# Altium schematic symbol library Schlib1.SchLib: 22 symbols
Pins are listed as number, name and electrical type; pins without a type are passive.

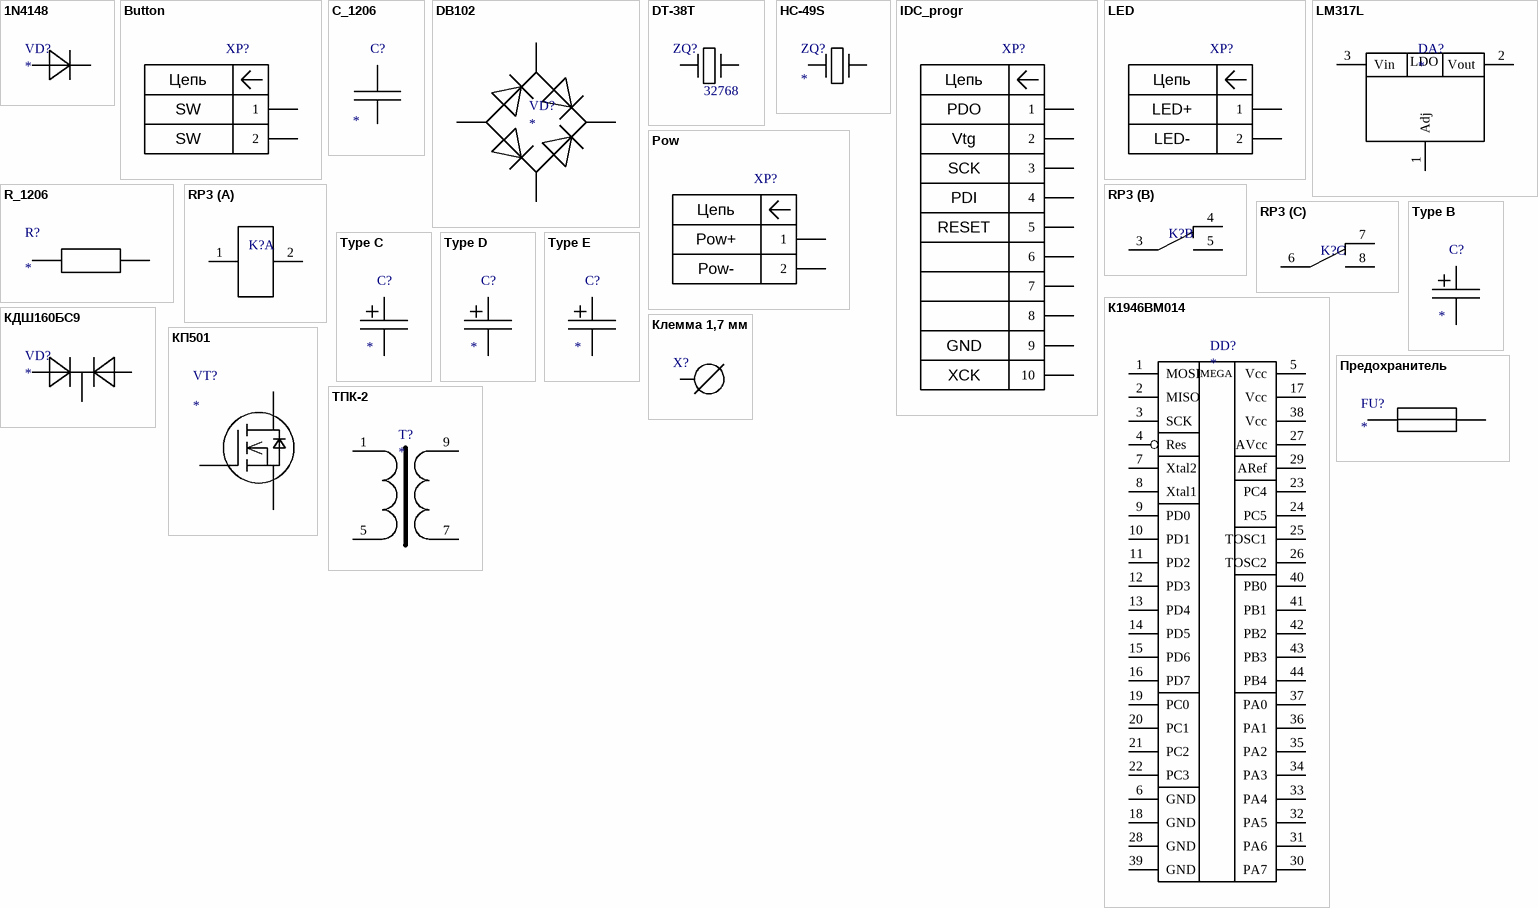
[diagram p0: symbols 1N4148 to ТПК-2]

## 1N4148
designator VD?
footprint DO-35
pins: 1, 2

## Button
designator XP?  (value not drawn)
footprint PLS-2
pins: 1, 2

## C_1206
designator C?
footprint RC_1206
pins: 1, 2

## DB102
designator VD?
footprint DB-1
pins: 1 AC, 2 AC, 3 +, 4 -

## DT-38T
designator ZQ?  value 32768  (hidden comment: *)
footprint DT-38T
pins: 1, 2

## HC-49S
designator ZQ?
footprint HC49-S
pins: 1, 2

## IDC_progr
designator XP?  (value not drawn)
footprint IDC-10MS
pins: 1, 2, 3, 4, 5, 6, 7, 8, 9, 10

## LED
designator XP?  (value not drawn)
footprint PLS-2
pins: 1, 2

## LM317L
designator DA?
footprint TO-92
pins: 1 Adj, 2 Vout, 3 Vin

## Pow
designator XP?  (value not drawn)
footprint PLS-2
pins: 1, 2

## R_1206
designator R?
footprint RC_1206
pins: 1, 2

## RP3
designator K?  (value not drawn)
footprint RP3
part A pins: 1, 2
part B pins: 3, 4, 5
part C pins: 6, 7, 8

## Type B
designator C?
footprint Type B
pins: 1, 2

## Type C
designator C?
footprint Type C
pins: 1, 2

## Type D
designator C?
footprint Type D
pins: 1, 2

## Type E
designator C?
footprint Type E
pins: 1, 2

## К1946ВМ014
designator DD?
footprint TQFP-44
pins: 1 MOSI, 2 MISO, 3 SCK, 4 Res, 5 Vcc, 6 GND, 7 Xtal2, 8 Xtal1, 9 PD0, 10 PD1, 11 PD2, 12 PD3, 13 PD4, 14 PD5, 15 PD6, 16 PD7, 17 Vcc, 18 GND, 19 PC0, 20 PC1, 21 PC2, 22 PC3, 23 PC4, 24 PC5, 25 TOSC1, 26 TOSC2, 27 AVcc, 28 GND, 29 ARef, 30 PA7, 31 PA6, 32 PA5, 33 PA4, 34 PA3, 35 PA2, 36 PA1, 37 PA0, 38 Vcc, 39 GND, 40 PB0, 41 PB1, 42 PB2, 43 PB3, 44 PB4

## КДШ160БС9
designator VD?
footprint SOT-23
pins: 1, 2, 3

## Клемма 1,7 мм
designator X?  (value not drawn)
footprint Клемма 1,7 мм
pins: 1

## КП501
designator VT?
footprint TO-92
pins: 1 gate, 2 drain, 3 sourse

## Предохранитель
designator FU?
footprint ВП2-1
pins: 1, 2

## ТПК-2
designator T?
footprint ТПГ-2
pins: 1, 5, 7, 9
